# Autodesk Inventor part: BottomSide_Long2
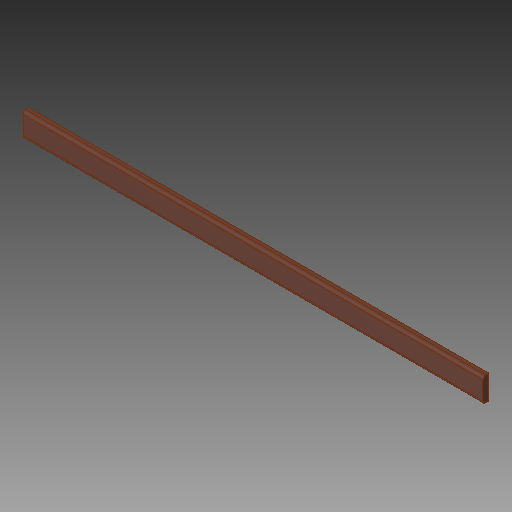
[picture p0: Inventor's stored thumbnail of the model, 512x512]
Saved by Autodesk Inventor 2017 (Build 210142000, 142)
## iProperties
Created: 2017-05
Part Number: BottomSide_Long2
Material: Generic
Document SubType Name: Modeling
Designer: Savy
Density: 1 g/cm^3
Appearance: Default
Mass: 622.988 g
Surface Area: 1218.66 cm^2
Volume: 622.988 cm^3
Author: Savy
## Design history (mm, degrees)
feature "SOLID1"
body "Solid1"
